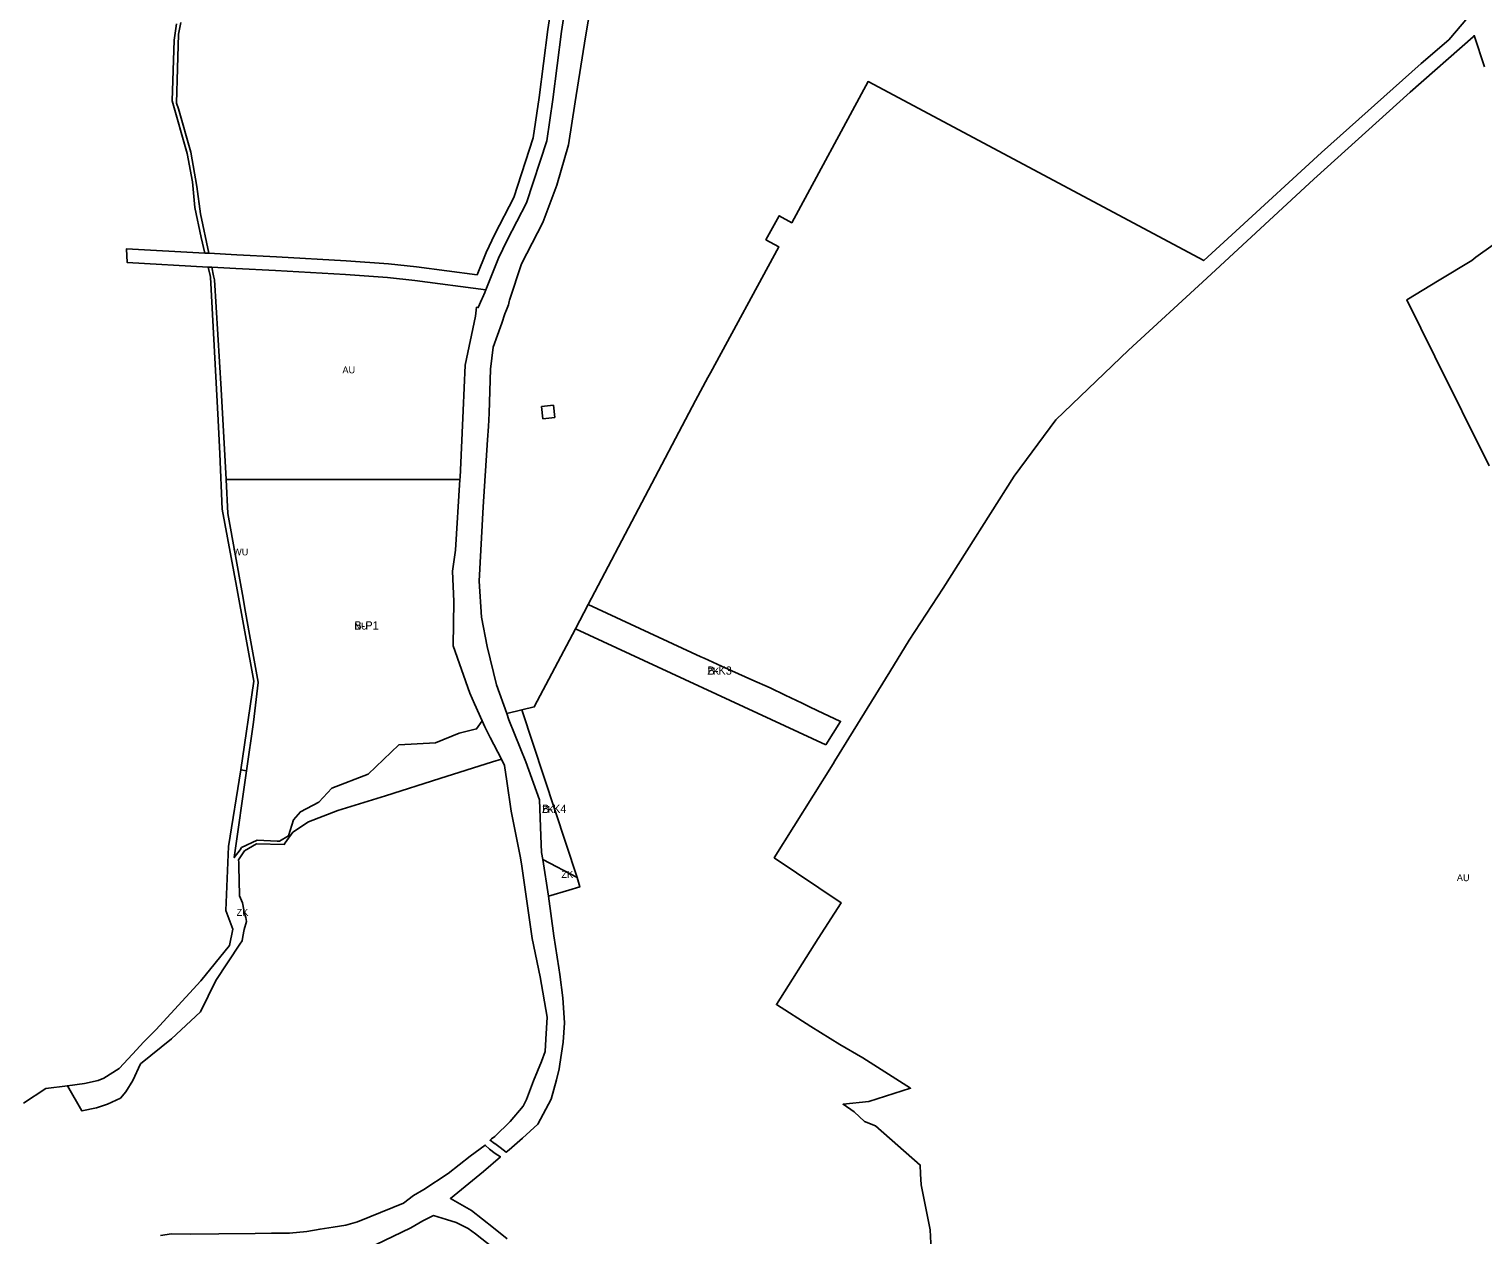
# Model space of a CAD drawing. Extents: x -532067 to -529270, y -1180561 to -1176456.
# Drawn here: x -530875 to -529815, y -1178117 to -1177238 of the extents above; entities that cross this region are included whole.
import ezdxf

# ---------------------------------------------------------------- set-up
doc = ezdxf.new("R2010")
doc.units = 0
for name, color, linetype in [('90630013', 7, 'Continuous'), ('90710013', 7, 'Continuous'), ('90710023', 7, 'Continuous'), ('90730023', 7, 'Continuous'), ('90750013', 7, 'Continuous'), ('ID_navrh', 7, 'Continuous')]:
    doc.layers.add(name, color=color, linetype=linetype)

msp = doc.modelspace()

# ---------------------------------------------------------------- linework, layer by layer
at = {"layer": '90630013'}
for points in [[(-530461.6683, -1177195.77945), (-530469.5993, -1177243.23545), (-530477.2563, -1177290.69245), (-530481.9833, -1177322.15245), (-530490.6373, -1177351.35145), (-530500.8653, -1177378.70845), (-530516.3373, -1177408.95945), (-530524.9463, -1177435.37545), (-530525.2543, -1177436.31745), (-530525.8383, -1177438.77145), (-530527.3473, -1177442.48545), (-530528.5503, -1177445.44845), (-530530.5233, -1177452.12645), (-530536.8763, -1177469.63045), (-530538.8103, -1177485.73145), (-530539.7773, -1177517.73845), (-530540.4543, -1177527.53445), (-530541.1313, -1177537.33045), (-530544.2983, -1177586.16045), (-530547.2663, -1177640.28845), (-530545.3773, -1177666.54045), (-530541.3543, -1177688.09245), (-530534.4443, -1177716.11945), (-530527.0103, -1177736.99545), (-530525.4303, -1177741.43445), (-530513.1123, -1177772.17345), (-530503.1983, -1177799.89945), (-530502.2973, -1177826.11745), (-530501.6503, -1177838.24945), (-530500.8113, -1177843.48845), (-530496.5303, -1177870.20745), (-530492.6063, -1177899.23245), (-530489.1413, -1177922.40445), (-530488.4483, -1177927.40945), (-530486.2483, -1177944.29045), (-530484.8593, -1177962.55745), (-530486.0203, -1177976.84045), (-530488.2473, -1177992.69945), (-530488.9153, -1177996.27345), (-530490.6963, -1178004.09145), (-530494.6633, -1178018.21945), (-530504.4163, -1178036.63645), (-530515.5923, -1178046.72545), (-530525.3313, -1178055.37345), (-530527.3933, -1178056.99245), (-530531.8453, -1178053.52845), (-530535.8623, -1178050.73945), (-530536.0123, -1178050.62945), (-530539.2083, -1178048.28945), (-530538.1823, -1178047.15445), (-530535.8393, -1178045.54545), (-530524.4913, -1178034.65845), (-530515.0673, -1178023.52545), (-530512.7613, -1178018.51045), (-530507.5343, -1178005.02045), (-530501.6653, -1177990.89145), (-530498.9263, -1177983.56545), (-530498.4773, -1177974.59045), (-530497.5273, -1177958.38745), (-530502.6283, -1177929.02645), (-530508.4383, -1177901.09845), (-530516.4183, -1177846.70745), (-530517.2123, -1177841.12945), (-530523.7273, -1177808.29445), (-530527.0693, -1177786.39845), (-530528.8123, -1177774.98245), (-530530.9773, -1177770.13845), (-530539.0383, -1177754.54345), (-530543.1373, -1177746.61345), (-530544.8743, -1177742.25745), (-530550.5203, -1177729.84245), (-530553.9603, -1177722.12945), (-530566.2513, -1177687.61045), (-530565.7593, -1177655.31045), (-530566.6373, -1177633.00845), (-530564.5173, -1177617.85945), (-530561.1703, -1177566.19345), (-530561.0733, -1177564.70345), (-530558.9533, -1177515.79945), (-530557.3753, -1177482.82145), (-530549.8333, -1177446.93445), (-530549.0143, -1177440.50245), (-530547.7813, -1177440.74945), (-530545.2743, -1177434.67045), (-530544.8233, -1177433.57745), (-530543.0973, -1177429.86845), (-530543.0723, -1177429.80645), (-530542.3203, -1177427.92945), (-530532.9883, -1177404.64245), (-530526.8243, -1177391.53445), (-530512.7543, -1177364.23845), (-530497.9153, -1177319.13345), (-530493.4183, -1177288.91245), (-530487.1233, -1177239.29545), (-530479.9283, -1177191.48345)], [(-530764.7433, -1177232.85045), (-530766.3243, -1177241.21445), (-530767.0563, -1177266.43445), (-530767.7883, -1177291.65545), (-530766.3533, -1177295.67845), (-530757.4123, -1177327.43145), (-530753.0623, -1177352.39845), (-530750.4043, -1177372.27445), (-530744.3213, -1177401.18245), (-530747.2313, -1177401.02545), (-530749.8703, -1177389.65445), (-530754.6013, -1177367.86945), (-530756.1083, -1177349.07945), (-530760.1993, -1177328.34445), (-530770.9653, -1177289.89945), (-530769.6093, -1177245.67445), (-530767.7953, -1177233.76245)], [(-530779.6063, -1178117.88345), (-530771.5433, -1178116.65245), (-530757.6973, -1178116.82845), (-530737.0153, -1178116.65245), (-530710.6293, -1178116.24345), (-530698.6793, -1178116.05845), (-530685.4413, -1178116.05845), (-530672.7543, -1178114.76745), (-530663.1943, -1178113.10745), (-530653.6333, -1178111.63245), (-530644.4403, -1178110.15745), (-530635.9823, -1178107.75945), (-530626.7903, -1178104.07145), (-530602.3383, -1178094.21045), (-530595.0463, -1178088.67545), (-530587.5583, -1178084.12945), (-530569.8913, -1178072.50245), (-530553.6323, -1178059.94545), (-530542.6973, -1178051.86345), (-530539.7053, -1178054.87845), (-530535.5073, -1178057.99445), (-530531.7033, -1178060.33845), (-530543.9963, -1178071.06845), (-530568.1433, -1178090.84445), (-530552.7723, -1178099.50645), (-530536.6333, -1178112.26445), (-530526.6923, -1178120.12245)], [(-530537.2423, -1178126.59945), (-530549.8433, -1178116.64645), (-530555.2253, -1178112.66845), (-530563.9283, -1178108.21045), (-530570.9643, -1178105.98245), (-530580.4083, -1178103.19645), (-530588.1773, -1178107.12945), (-530597.0133, -1178112.12145), (-530622.6703, -1178124.54545)]]:
    msp.add_lwpolyline(points, dxfattribs=at)
msp.add_lwpolyline([(-530711.7323, -1177743.27845), (-530716.7613, -1177778.72545), (-530721.0713, -1177777.99645), (-530711.3873, -1177713.36945), (-530724.2453, -1177644.04445), (-530734.6563, -1177587.73645), (-530736.1873, -1177547.59845), (-530737.4993, -1177523.03345), (-530743.1753, -1177418.50645), (-530743.4213, -1177417.44445), (-530744.8773, -1177411.16945), (-530742.1893, -1177411.31445), (-530740.8863, -1177417.51345), (-530740.2553, -1177420.51045), (-530735.4223, -1177500.26045), (-530731.5553, -1177566.19345), (-530730.3473, -1177590.91845), (-530719.8483, -1177650.05845), (-530717.5493, -1177663.01045), (-530714.6403, -1177679.39445), (-530708.4043, -1177714.04045), (-530708.3573, -1177714.30045)], close=True, dxfattribs=at)
at = {"layer": '90710013'}
for points in [[(-530682.9803, -1177823.50345), (-530688.5573, -1177831.34045), (-530689.3413, -1177832.44145), (-530709.5523, -1177832.07345), (-530718.3713, -1177837.23345), (-530722.5973, -1177843.68445), (-530722.5403, -1177845.72545), (-530722.0893, -1177861.89045), (-530721.9583, -1177866.60745), (-530721.8623, -1177870.03945), (-530719.7973, -1177875.18445), (-530718.8563, -1177880.21845), (-530718.4383, -1177882.21145), (-530717.2883, -1177885.88245), (-530716.7173, -1177888.65345), (-530718.4333, -1177894.56345), (-530719.4713, -1177899.51845), (-530719.9673, -1177902.75145), (-530721.6223, -1177905.25045), (-530739.2283, -1177931.83945), (-530750.2933, -1177954.51845), (-530771.4593, -1177974.30245), (-530794.0693, -1177992.63845), (-530799.8413, -1178004.70245), (-530804.8933, -1178012.87345), (-530808.7743, -1178017.47445), (-530818.3013, -1178022.07545), (-530826.2403, -1178024.72945), (-530836.8253, -1178026.85245), (-530847.4103, -1178008.47045), (-530834.9103, -1178006.80845), (-530825.0653, -1178004.76545), (-530820.9913, -1178003.06245), (-530809.7883, -1177995.91145), (-530799.9433, -1177985.35545), (-530791.7963, -1177976.50145), (-530783.0193, -1177967.70045), (-530750.1173, -1177932.02645), (-530729.2793, -1177906.09545), (-530726.9063, -1177894.23145), (-530731.9083, -1177880.57345), (-530729.9633, -1177834.02345), (-530721.0713, -1177777.99645), (-530716.7613, -1177778.72545), (-530725.7413, -1177842.01345), (-530721.5463, -1177836.35445), (-530720.3953, -1177834.80245), (-530708.9673, -1177829.25545), (-530694.5893, -1177829.99545), (-530692.6883, -1177830.07545), (-530686.2333, -1177826.23145), (-530682.6023, -1177814.49545), (-530677.5593, -1177808.62745), (-530664.0433, -1177801.54545), (-530654.5623, -1177791.42745), (-530628.1363, -1177781.31045), (-530605.7453, -1177759.86245), (-530578.9163, -1177758.44545), (-530561.7693, -1177751.16145), (-530549.0603, -1177748.12645), (-530544.8743, -1177742.25745), (-530543.1373, -1177746.61345), (-530539.0383, -1177754.54345), (-530530.9773, -1177770.13845), (-530537.4563, -1177772.19345), (-530575.8403, -1177784.36745), (-530615.4473, -1177796.92945), (-530650.1913, -1177807.60245), (-530671.6883, -1177815.87945)], [(-530481.9033, -1177865.72045), (-530496.5303, -1177870.20745), (-530500.8113, -1177843.48845), (-530475.7313, -1177856.67645), (-530473.8043, -1177863.39945)]]:
    msp.add_lwpolyline(points, close=True, dxfattribs=at)
at = {"layer": '90710023'}
for points in [[(-530294.4153, -1177759.74045), (-530477.0183, -1177675.19345), (-530467.6893, -1177657.47245), (-530385.4313, -1177695.55945), (-530383.0843, -1177696.44245), (-530370.4663, -1177702.32945), (-530358.1413, -1177707.92145), (-530348.4583, -1177712.33645), (-530334.9603, -1177718.22345), (-530324.1023, -1177723.52145), (-530311.5343, -1177729.32645), (-530306.2033, -1177732.05745), (-530300.6273, -1177734.70645), (-530283.6203, -1177742.69945)], [(-530513.1123, -1177772.17345), (-530525.4303, -1177741.43445), (-530527.0103, -1177736.99545), (-530516.0613, -1177734.31645), (-530475.7313, -1177856.67645), (-530500.8113, -1177843.48845), (-530501.6503, -1177838.24945), (-530502.2973, -1177826.11745), (-530503.1983, -1177799.89945)]]:
    msp.add_lwpolyline(points, close=True, dxfattribs=at)
at = {"layer": '90730023'}
msp.add_lwpolyline([(-530561.1703, -1177566.19345), (-530564.5173, -1177617.85945), (-530566.6373, -1177633.00845), (-530565.7593, -1177655.31045), (-530566.2513, -1177687.61045), (-530553.9603, -1177722.12945), (-530550.5203, -1177729.84245), (-530544.8743, -1177742.25745), (-530549.0603, -1177748.12645), (-530561.7693, -1177751.16145), (-530578.9163, -1177758.44545), (-530605.7453, -1177759.86245), (-530628.1363, -1177781.31045), (-530654.5623, -1177791.42745), (-530664.0433, -1177801.54545), (-530677.5593, -1177808.62745), (-530682.6023, -1177814.49545), (-530686.2333, -1177826.23145), (-530692.6883, -1177830.07545), (-530694.5893, -1177829.99545), (-530708.9673, -1177829.25545), (-530720.3953, -1177834.80245), (-530721.5463, -1177836.35445), (-530725.7413, -1177842.01345), (-530716.7613, -1177778.72545), (-530711.7323, -1177743.27845), (-530708.3573, -1177714.30045), (-530708.4043, -1177714.04045), (-530714.6403, -1177679.39445), (-530717.5493, -1177663.01045), (-530719.8483, -1177650.05845), (-530730.3473, -1177590.91845), (-530731.5553, -1177566.19345)], close=True, dxfattribs=at)
at = {"layer": '90750013'}
for points in [[(-530489.6373, -1177188.80345), (-530497.0293, -1177237.92145), (-530503.3253, -1177287.54645), (-530507.6803, -1177316.81845), (-530522.0053, -1177360.36045), (-530535.7963, -1177387.11445), (-530542.1623, -1177400.65145), (-530548.7063, -1177416.98145), (-530592.9143, -1177411.03845), (-530613.2283, -1177408.77445), (-530644.0673, -1177406.77845), (-530695.0343, -1177403.84845), (-530724.0073, -1177402.28345), (-530744.3213, -1177401.18245), (-530750.4043, -1177372.27445), (-530753.0623, -1177352.39845), (-530757.4123, -1177327.43145), (-530766.3533, -1177295.67845), (-530767.7883, -1177291.65545), (-530767.0563, -1177266.43445), (-530766.3243, -1177241.21445), (-530764.7433, -1177232.85045)], [(-529826.2783, -1177229.04845), (-529840.1833, -1177245.45745), (-529860.3593, -1177262.68745), (-529932.8373, -1177327.59345), (-529995.3763, -1177385.07345), (-530018.7833, -1177406.52245), (-530263.5453, -1177275.83445), (-530319.2523, -1177378.82945), (-530328.3473, -1177373.79045), (-530338.0403, -1177391.28445), (-530328.7673, -1177396.42245), (-530378.5063, -1177488.38645), (-530379.3893, -1177490.01845), (-530379.4103, -1177490.05845), (-530379.4193, -1177490.07445), (-530380.3753, -1177491.86445), (-530389.2993, -1177508.57545), (-530467.6893, -1177657.47245), (-530477.0183, -1177675.19345), (-530506.9743, -1177732.09345), (-530516.0613, -1177734.31645), (-530527.0103, -1177736.99545), (-530534.4443, -1177716.11945), (-530541.3543, -1177688.09245), (-530545.3773, -1177666.54045), (-530547.2663, -1177640.28845), (-530544.2983, -1177586.16045), (-530541.1313, -1177537.33045), (-530540.4543, -1177527.53445), (-530539.7773, -1177517.73845), (-530538.8103, -1177485.73145), (-530536.8763, -1177469.63045), (-530530.5233, -1177452.12645), (-530528.5503, -1177445.44845), (-530527.3473, -1177442.48545), (-530525.8383, -1177438.77145), (-530525.2543, -1177436.31745), (-530524.9463, -1177435.37545), (-530516.3373, -1177408.95945), (-530500.8653, -1177378.70845), (-530490.6373, -1177351.35145), (-530481.9833, -1177322.15245), (-530477.2563, -1177290.69245), (-530469.5993, -1177243.23545), (-530461.6683, -1177195.77945)], [(-530767.7953, -1177233.76245), (-530769.6093, -1177245.67445), (-530770.9653, -1177289.89945), (-530760.1993, -1177328.34445), (-530756.1083, -1177349.07945), (-530754.6013, -1177367.86945), (-530749.8703, -1177389.65445), (-530747.2313, -1177401.02545), (-530804.4423, -1177397.92445), (-530803.8453, -1177407.97145), (-530744.8773, -1177411.16945), (-530743.4213, -1177417.44445), (-530743.1753, -1177418.50645), (-530737.4993, -1177523.03345), (-530736.1873, -1177547.59845), (-530734.6563, -1177587.73645), (-530724.2453, -1177644.04445), (-530711.3873, -1177713.36945), (-530721.0713, -1177777.99645), (-530729.9633, -1177834.02345), (-530731.9083, -1177880.57345), (-530726.9063, -1177894.23145), (-530729.2793, -1177906.09545), (-530750.1173, -1177932.02645), (-530783.0193, -1177967.70045), (-530791.7963, -1177976.50145), (-530799.9433, -1177985.35545), (-530809.7883, -1177995.91145), (-530820.9913, -1178003.06245), (-530825.0653, -1178004.76545), (-530834.9103, -1178006.80845), (-530847.4103, -1178008.47045), (-530863.0883, -1178010.55445), (-530879.3833, -1178021.11145)], [(-530217.2033, -1178137.99345), (-530218.2293, -1178113.53445), (-530224.8663, -1178080.68945), (-530225.2533, -1178072.81645), (-530225.5703, -1178066.36445), (-530258.2183, -1178037.84645), (-530266.2133, -1178034.52145), (-530273.8173, -1178027.48045), (-530281.8123, -1178022.00345), (-530263.1133, -1178020.00045), (-530232.5793, -1178010.35345), (-530267.4413, -1177988.16645), (-530284.2703, -1177978.51945), (-530305.4283, -1177965.25545), (-530330.4503, -1177949.33845), (-530299.8523, -1177901.09145), (-530283.3193, -1177875.02245), (-530332.0333, -1177842.15945), (-530288.9793, -1177773.56145), (-530287.7503, -1177771.56645), (-530247.7753, -1177706.64445), (-530233.5283, -1177683.50645), (-530208.8843, -1177645.54245), (-530157.0203, -1177563.79845), (-530126.7073, -1177522.55345), (-530073.7763, -1177471.92045), (-530016.5393, -1177419.42845), (-529938.4963, -1177347.17945), (-529868.1993, -1177283.68845), (-529822.2913, -1177243.34745), (-529821.5733, -1177242.29045), (-529814.1763, -1177265.18145)], [(-529793.3993, -1177384.71945), (-529820.5053, -1177404.11045), (-529823.4153, -1177406.33745), (-529847.2403, -1177420.82145), (-529870.7883, -1177435.22545), (-529850.3993, -1177476.42045), (-529810.6643, -1177556.14645)]]:
    msp.add_lwpolyline(points, dxfattribs=at)
for points in [[(-530545.2743, -1177434.67045), (-530547.7813, -1177440.74945), (-530549.0143, -1177440.50245), (-530549.8333, -1177446.93445), (-530557.3753, -1177482.82145), (-530558.9533, -1177515.79945), (-530561.0733, -1177564.70345), (-530561.1703, -1177566.19345), (-530731.5553, -1177566.19345), (-530735.4223, -1177500.26045), (-530740.2553, -1177420.51045), (-530740.8863, -1177417.51345), (-530742.1893, -1177411.31445), (-530724.5473, -1177412.26945), (-530695.5913, -1177413.83345), (-530644.6773, -1177416.76045), (-530614.1053, -1177418.73845), (-530594.1343, -1177420.96445), (-530542.3203, -1177427.92945), (-530543.0723, -1177429.80645), (-530543.0973, -1177429.86845), (-530544.8233, -1177433.57745)], [(-530501.6213, -1177512.95645), (-530500.6493, -1177521.89845), (-530492.0203, -1177520.96045), (-530492.9923, -1177512.01845)]]:
    msp.add_lwpolyline(points, close=True, dxfattribs=at)

# ---------------------------------------------------------------- texts
at = {"layer": '90630013'}
msp.add_text('WU', height=5, rotation=359.99999996, dxfattribs=at).set_placement((-530726.6173, -1177621.57235))
at = {"layer": '90710013'}
for rotation, p in [(359.99999998, (-530487.17647, -1177856.84795)), (0.00000003, (-530724.07715, -1177884.55495))]:
    msp.add_text('ZK', height=5, rotation=rotation, dxfattribs=at).set_placement(p)
at = {"layer": '90710023'}
for rotation, p in [(0.00000001, (-530380.74625, -1177708.60645)), (359.99999996, (-530501.3708, -1177809.44086))]:
    msp.add_text('ZK', height=5, rotation=rotation, dxfattribs=at).set_placement(p)
at = {"layer": '90730023'}
msp.add_text('NU', height=5, rotation=359.99999999, dxfattribs=at).set_placement((-530638.2148, -1177675.68119))
at = {"layer": '90750013'}
for rotation, p in [(359.99999997, (-530646.88939, -1177488.75395)), (0.00000005, (-529834.25117, -1177859.24495))]:
    msp.add_text('AU', height=5, rotation=rotation, dxfattribs=at).set_placement(p)
at = {"layer": 'ID_navrh'}
for s, rotation, p in [('B-P1', 0.00000003, (-530638.2148, -1177675.68119)), ('B-K3', 359.99999994, (-530380.74625, -1177708.60645)), ('B-K4', 359.99999998, (-530501.3708, -1177809.44086))]:
    msp.add_text(s, height=6, rotation=rotation, dxfattribs=at).set_placement(p)

doc.saveas('drawing.dxf')
